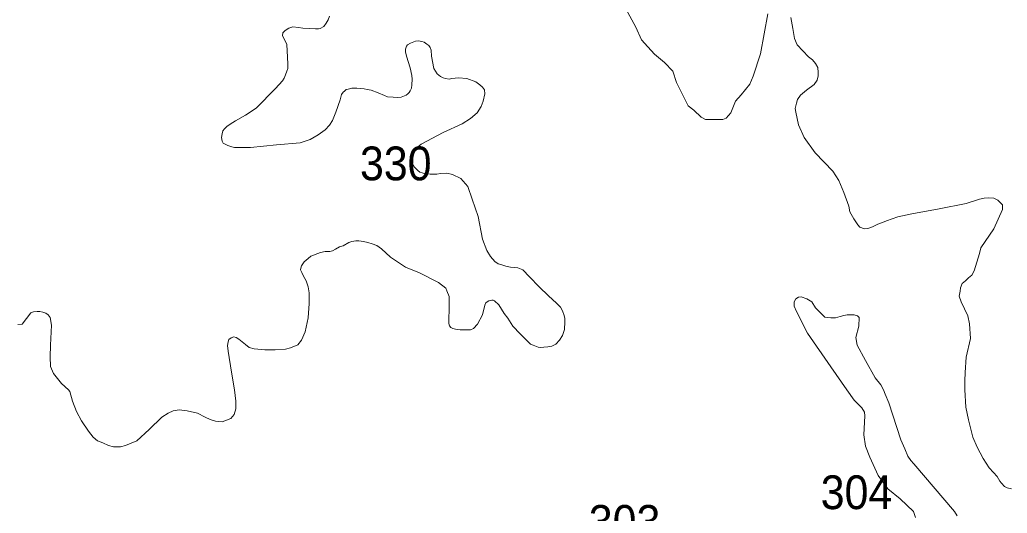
# Model space of a CAD drawing. Extents: x 445.4 to 500, y 8728.7 to 8784.
# Drawn here: x 471.621 to 476.303, y 8755.732 to 8758.07 of the extents above; entities that cross this region are included whole.
import ezdxf

# ---------------------------------------------------------------- set-up
doc = ezdxf.new("R2010")
doc.units = 0
doc.header["$LTSCALE"] = 0.064
doc.layers.add('2', color=7, linetype='Continuous', lineweight=13)
doc.layers.add('21', color=7, linetype='Continuous')

msp = doc.modelspace()

# ---------------------------------------------------------------- linework, layer by layer
at = {"layer": '2'}
for points in [[(474.4853, 8758.139), (474.5412, 8758.0356), (474.5692, 8757.9757), (474.5992, 8757.9426), (474.6305, 8757.9078), (474.677, 8757.8675), (474.7164, 8757.8272), (474.735, 8757.7724), (474.7899, 8757.6617), (474.817, 8757.6425), (474.8522, 8757.6084), (474.8718, 8757.598), (474.8915, 8757.598), (474.9277, 8757.597), (474.9536, 8757.597), (474.9702, 8757.6032), (474.9929, 8757.6291), (475.0136, 8757.6849), (475.0406, 8757.7149), (475.082, 8757.7645), (475.0978, 8757.8036), (475.133, 8757.909), (475.1496, 8758.0031), (475.1673, 8758.0988)], [(472.6787, 8757.4648), (472.6393, 8757.4648), (472.6258, 8757.4684), (472.6076, 8757.4742), (472.5977, 8757.4787), (472.5861, 8757.485), (472.5861, 8757.485), (472.5807, 8757.4949), (472.578, 8757.5119), (472.5807, 8757.5298), (472.5843, 8757.5432), (472.5924, 8757.554), (472.6022, 8757.5639), (472.6193, 8757.5755), (472.6444, 8757.5916), (472.6911, 8757.6185), (472.7413, 8757.6517), (472.8337, 8757.744), (472.8663, 8757.7805), (472.8744, 8757.7939), (472.8816, 8757.81), (472.8879, 8757.8271), (472.8915, 8757.8396), (472.8924, 8757.8602), (472.8906, 8757.8934), (472.8879, 8757.9534), (472.8736, 8757.9827), (472.8673, 8757.9934), (472.8682, 8758.0078), (472.8798, 8758.0194), (472.8969, 8758.0311), (472.9157, 8758.0364), (472.9426, 8758.0338), (472.9624, 8758.0311), (473.0234, 8758.0275), (473.0377, 8758.0266), (473.0458, 8758.0293), (473.062, 8758.0382), (473.0736, 8758.0535), (473.0835, 8758.0696), (473.0889, 8758.0875)], [(475.277, 8758.0813), (475.2853, 8758.0285), (475.2936, 8757.981), (475.3073, 8757.9513), (475.3601, 8757.8944), (475.3797, 8757.88), (475.3932, 8757.8624), (475.4046, 8757.8438), (475.4066, 8757.821), (475.4066, 8757.8045), (475.4015, 8757.7848), (475.387, 8757.7631), (475.3508, 8757.7373), (475.3218, 8757.7135), (475.3081, 8757.6932), (475.304, 8757.6756), (475.2978, 8757.6498), (475.3009, 8757.6322), (475.3123, 8757.5722), (475.3392, 8757.5122), (475.3921, 8757.4397), (475.475, 8757.3522), (475.5046, 8757.3084), (475.5283, 8757.2516), (475.552, 8757.1866), (475.5556, 8757.1594), (475.5745, 8757.1274), (475.5938, 8757.0992), (475.6033, 8757.0873), (475.6258, 8757.0802), (475.6423, 8757.0814), (475.6637, 8757.0897), (475.6885, 8757.1015), (475.711, 8757.1098), (475.73, 8757.1181), (475.7845, 8757.1358), (475.8501, 8757.1505), (475.9804, 8757.1741), (476.1083, 8757.199), (476.171, 8757.2203), (476.1924, 8757.225), (476.2149, 8757.2262), (476.2385, 8757.225), (476.2587, 8757.2155), (476.2681, 8757.2061), (476.28, 8757.1931), (476.28, 8757.1718), (476.2397, 8757.0795), (476.177, 8756.9896), (476.1712, 8756.9627), (476.1451, 8756.8811), (476.1344, 8756.8598), (476.119, 8756.8479), (476.1048, 8756.8337), (476.0894, 8756.8207), (476.0811, 8756.8006), (476.0788, 8756.7841), (476.0752, 8756.7604), (476.0847, 8756.7332), (476.1155, 8756.6669), (476.1238, 8756.6291), (476.1285, 8756.5605), (476.1084, 8756.4721), (476.1025, 8756.3987), (476.1013, 8756.3597), (476.1013, 8756.3168), (476.1013, 8756.3168)], [(473.8736, 8756.9249), (473.8529, 8756.9482), (473.835, 8756.9769), (473.8144, 8757.0307), (473.7935, 8757.1379), (473.7666, 8757.2195), (473.7459, 8757.2804), (473.7125, 8757.3178), (473.6721, 8757.3375), (473.6452, 8757.3438), (473.6156, 8757.3411), (473.5985, 8757.3393), (473.5815, 8757.3384), (473.5662, 8757.3384), (473.5519, 8757.3402), (473.5375, 8757.342), (473.5295, 8757.3447), (473.5178, 8757.3474), (473.5088, 8757.3564), (473.4927, 8757.3716), (473.4855, 8757.3832), (473.4765, 8757.4012), (473.4747, 8757.4101), (473.472, 8757.4191), (473.4729, 8757.4298), (473.4792, 8757.4424), (473.4909, 8757.454), (473.5241, 8757.4809), (473.629, 8757.5356), (473.719, 8757.5774), (473.7576, 8757.6025), (473.789, 8757.6294), (473.8087, 8757.6589), (473.8186, 8757.684), (473.8257, 8757.719), (473.824, 8757.7378), (473.815, 8757.7512), (473.8024, 8757.762), (473.7827, 8757.7763), (473.7405, 8757.7925), (473.7009, 8757.7948), (473.6856, 8757.793), (473.6695, 8757.7913), (473.656, 8757.7886), (473.6399, 8757.7913), (473.6291, 8757.7948), (473.6157, 8757.8011), (473.6004, 8757.8137), (473.5843, 8757.8388), (473.5726, 8757.8979), (473.5708, 8757.9257), (473.5663, 8757.9391), (473.5609, 8757.9481), (473.5511, 8757.9553), (473.5385, 8757.9633), (473.5277, 8757.9678), (473.5116, 8757.9705), (473.4972, 8757.9696), (473.4739, 8757.9597), (473.4595, 8757.9517), (473.4542, 8757.9454), (473.4497, 8757.9311), (473.4497, 8757.9176), (473.4542, 8757.897), (473.4721, 8757.8432), (473.4793, 8757.8056), (473.4811, 8757.7895), (473.4802, 8757.7617), (473.4784, 8757.7465), (473.4721, 8757.7339), (473.4667, 8757.7258), (473.4604, 8757.7196), (473.4533, 8757.7124), (473.4293, 8757.7029), (473.4114, 8757.702), (473.3907, 8757.7037), (473.3647, 8757.7046), (473.3504, 8757.7118), (473.3199, 8757.7244), (473.2876, 8757.7369), (473.2687, 8757.7405), (473.2535, 8757.7432), (473.2364, 8757.745), (473.2185, 8757.7459), (473.1952, 8757.7459), (473.1781, 8757.7414), (473.1691, 8757.7396), (473.1611, 8757.7324), (473.1548, 8757.727), (473.1467, 8757.7154), (473.1404, 8757.6912), (473.1198, 8757.6321), (473.1037, 8757.5926), (473.0893, 8757.5711), (473.0696, 8757.5487), (473.0358, 8757.5258), (472.9972, 8757.5025), (472.9506, 8757.4872), (472.8384, 8757.4783), (472.7155, 8757.4657), (472.6787, 8757.4648)], [(472.6465, 8756.5655), (472.6595, 8756.5565), (472.6905, 8756.5315), (472.7094, 8756.5176), (472.7324, 8756.5116), (472.7833, 8756.5056), (472.8143, 8756.5056), (472.8322, 8756.5056), (472.8812, 8756.5096), (472.9048, 8756.5161), (472.9398, 8756.5301), (472.9567, 8756.552), (472.9747, 8756.5909), (472.9887, 8756.6577), (472.9937, 8756.7265), (472.9937, 8756.7771), (472.9887, 8756.8041), (472.9787, 8756.834), (472.9668, 8756.8559), (472.9578, 8756.8729), (472.9518, 8756.8848), (472.9528, 8756.8928), (472.9568, 8756.9038), (472.9697, 8756.9227), (472.9887, 8756.9397), (473.0017, 8756.9507), (473.0466, 8756.9676), (473.0686, 8756.9716), (473.0916, 8756.9726), (473.1035, 8756.9746), (473.1185, 8756.9826), (473.1365, 8756.9936), (473.1545, 8756.9995), (473.1814, 8757.0145), (473.1954, 8757.0195), (473.2144, 8757.0225), (473.2293, 8757.0235), (473.2503, 8757.0195), (473.2713, 8757.0155), (473.2922, 8757.0085), (473.3142, 8757.0005), (473.3352, 8756.9856), (473.3791, 8756.9457), (473.4498, 8756.8987), (473.5157, 8756.8718), (473.6065, 8756.8259), (473.6405, 8756.799), (473.6465, 8756.7851), (473.6565, 8756.7591), (473.6575, 8756.7053), (473.6556, 8756.6457), (473.6556, 8756.6307), (473.6586, 8756.6207), (473.6646, 8756.6128), (473.6745, 8756.6078), (473.6875, 8756.6038), (473.7085, 8756.6008), (473.7574, 8756.6018), (473.7724, 8756.6068), (473.7914, 8756.6287), (473.8153, 8756.6726), (473.8263, 8756.7185), (473.8303, 8756.7294), (473.837, 8756.7341), (473.8441, 8756.7382), (473.8504, 8756.7407), (473.8592, 8756.7411), (473.8654, 8756.7411), (473.8725, 8756.7382), (473.8921, 8756.7191), (473.9168, 8756.6778), (473.9347, 8756.6565), (473.9591, 8756.6183), (473.9929, 8756.5825), (474.0417, 8756.5325), (474.0552, 8756.5277), (474.079, 8756.5189), (474.0911, 8756.5181), (474.1049, 8756.5185), (474.1241, 8756.5206), (474.1441, 8756.5235), (474.1617, 8756.5331), (474.1792, 8756.5518), (474.1934, 8756.5735), (474.204, 8756.6022), (474.2048, 8756.6384), (474.2048, 8756.6543), (474.2015, 8756.6697), (474.1939, 8756.6908), (474.1839, 8756.7087), (474.1664, 8756.7279), (474.1272, 8756.7629), (474.0827, 8756.8052), (474.038, 8756.8515), (474.0067, 8756.8853), (473.983, 8756.8945), (473.948, 8756.8981), (473.9247, 8756.9025), (473.9068, 8756.9088), (473.8897, 8756.9142), (473.8736, 8756.9249)], [(475.8682, 8755.712), (475.8581, 8755.7398), (475.7949, 8755.8004), (475.7367, 8755.8483), (475.6912, 8755.9114), (475.6507, 8755.9973), (475.6305, 8756.0503), (475.6229, 8756.1033), (475.628, 8756.1929), (475.6254, 8756.2106), (475.6128, 8756.2308), (475.5774, 8756.2686), (475.542, 8756.3166), (475.4656, 8756.4259), (475.3555, 8756.5858), (475.3029, 8756.6882), (475.2929, 8756.7132), (475.2929, 8756.7332), (475.3004, 8756.7482), (475.3129, 8756.7556), (475.3254, 8756.7581), (475.353, 8756.7482), (475.3603, 8756.7433), (475.3755, 8756.7336), (475.3942, 8756.7052), (475.4128, 8756.6858), (475.4371, 8756.6616), (475.4491, 8756.6592), (475.4666, 8756.6575), (475.4876, 8756.6578), (475.5103, 8756.664), (475.5278, 8756.6695), (475.5429, 8756.6716), (475.5642, 8756.6719), (475.5773, 8756.6723), (475.5932, 8756.6671)], [(471.6116, 8756.627), (471.6317, 8756.6285), (471.674, 8756.6819), (471.6868, 8756.6867), (471.7043, 8756.6883), (471.7155, 8756.6883), (471.7298, 8756.6851), (471.7442, 8756.6803), (471.7554, 8756.6724), (471.7649, 8756.6596), (471.7713, 8756.623), (471.7665, 8756.529), (471.7649, 8756.4733), (471.7665, 8756.4271), (471.7809, 8756.3937), (471.8191, 8756.3475), (471.8516, 8756.3168), (471.8581, 8756.3086), (471.8711, 8756.2632), (471.8906, 8756.2134), (471.9144, 8756.1702), (471.9469, 8756.1204), (471.9686, 8756.0923), (471.9903, 8756.075), (472.0141, 8756.0663), (472.0423, 8756.0534), (472.0661, 8756.0469), (472.0986, 8756.0469), (472.1225, 8756.0534), (472.1766, 8756.075), (472.2352, 8756.1291), (472.2948, 8756.1873), (472.3251, 8756.2068), (472.349, 8756.2176), (472.3771, 8756.2219), (472.414, 8756.2176), (472.4638, 8756.2068), (472.5007, 8756.1873), (472.5245, 8756.1765), (472.5484, 8756.1679), (472.5809, 8756.1657), (472.622, 8756.1808), (472.6372, 8756.2003), (472.6459, 8756.2263), (472.6459, 8756.263), (472.6393, 8756.3168), (472.6246, 8756.4009), (472.6096, 8756.5006), (472.6066, 8756.5276), (472.6086, 8756.5435), (472.6116, 8756.5545), (472.6236, 8756.5635), (472.6355, 8756.5674), (472.6465, 8756.5655)], [(475.5932, 8756.6671), (475.6013, 8756.6596), (475.5989, 8756.6183), (475.5852, 8756.5654), (475.5903, 8756.5282), (475.6308, 8756.4559), (475.6758, 8756.3734), (475.7034, 8756.3409), (475.7163, 8756.3168), (475.7242, 8756.2957), (475.7415, 8756.2554), (475.7978, 8756.0802), (475.8178, 8756.038), (475.8315, 8756.0021), (475.8457, 8755.9817), (475.8596, 8755.9659), (476.0526, 8755.7406), (476.0646, 8755.7192)], [(476.1013, 8756.3168), (476.1068, 8756.2352), (476.1194, 8756.1743), (476.1392, 8756.0918), (476.1607, 8756.0451), (476.1879, 8755.992), (476.2166, 8755.9472), (476.2382, 8755.9256), (476.2555, 8755.9056), (476.267, 8755.8839), (476.2747, 8755.875), (476.29, 8755.8584), (476.3015, 8755.852), (476.3232, 8755.8482)]]:
    msp.add_lwpolyline(points, dxfattribs=at)

# ---------------------------------------------------------------- texts
at = {"layer": '21', "width": 0.95}
for s, p in [('330', (473.234, 8757.3096)), ('304', (475.4183, 8755.7515)), ('303', (474.3189, 8755.611))]:
    msp.add_text(s, height=0.16, dxfattribs=at).set_placement(p)

doc.saveas('drawing.dxf')
